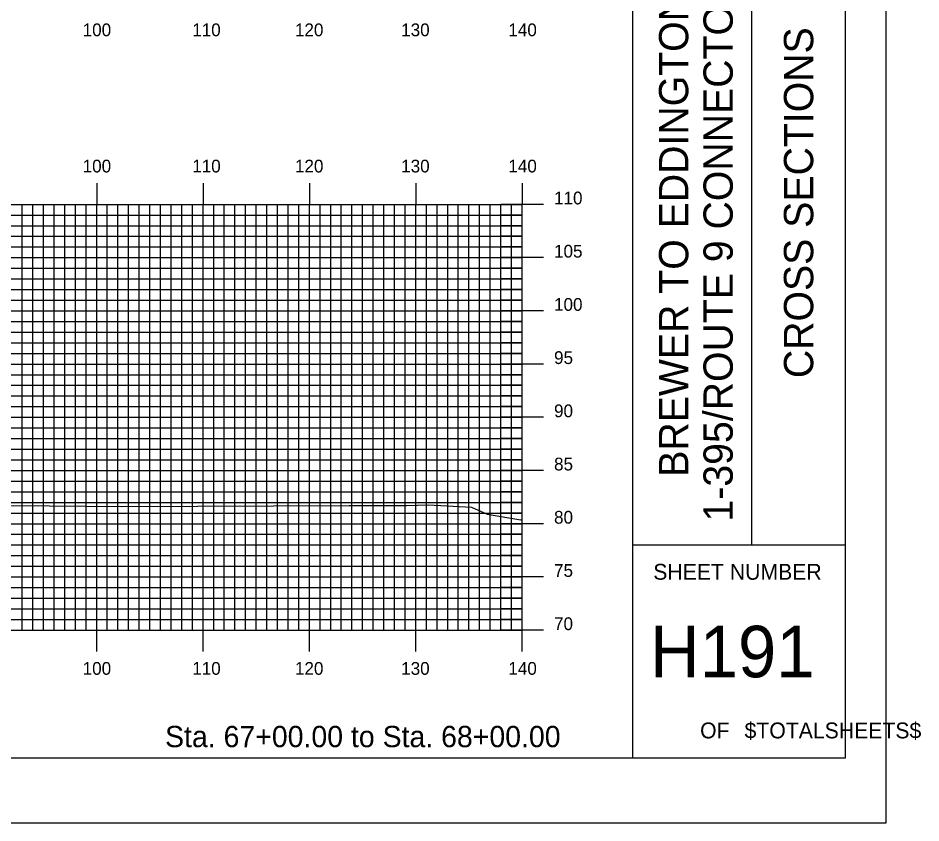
# Model space of a CAD drawing. Extents: x 1759430 to 1759773, y 442591 to 442811.
# Drawn here: x 1759688.3 to 1759773.2, y 442590.5 to 442666.2 of the extents above; entities that cross this region are included whole.
import ezdxf

# ---------------------------------------------------------------- set-up
doc = ezdxf.new("R2010")
doc.units = 0
for name, color, linetype in [('BORDER', 7, 'Continuous'), ('H_V ANNOTATION', 7, 'Continuous'), ('MAJOR', 7, 'Continuous'), ('MINOR', 7, 'Continuous'), ('PLOT BOUNDARY', 7, 'Continuous'), ('S_Roadway_Centerline', 7, 'Continuous')]:
    doc.layers.add(name, color=color, linetype=linetype)

msp = doc.modelspace()

# ---------------------------------------------------------------- linework, layer by layer
at = {"layer": 'BORDER'}
for p, q in [((1759746.075, 442596.665), (1759746.075, 442806.665)), ((1759757.257, 442616.671), (1759757.257, 442686.671)), ((1759746.075, 442616.671), (1759766.075, 442616.671))]:
    msp.add_line(p, q, dxfattribs=at)
msp.add_lwpolyline([(1759446.075, 442596.665), (1759766.075, 442596.665), (1759766.075, 442806.665), (1759446.075, 442806.665)], close=True, dxfattribs=at)
at = {"layer": 'MAJOR'}
for p, q in [((1759695.675, 442650.669), (1759695.675, 442648.665)), ((1759705.675, 442650.669), (1759705.675, 442648.665)), ((1759715.675, 442650.669), (1759715.675, 442648.665)), ((1759725.675, 442650.669), (1759725.675, 442648.665)), ((1759735.675, 442650.669), (1759735.675, 442648.665)), ((1759455.675, 442648.665), (1759735.675, 442648.665)), ((1759455.675, 442648.665), (1759735.675, 442648.665)), ((1759695.675, 442608.665), (1759695.675, 442648.665)), ((1759705.675, 442608.665), (1759705.675, 442648.665)), ((1759715.675, 442608.665), (1759715.675, 442648.665)), ((1759725.675, 442608.665), (1759725.675, 442648.665)), ((1759737.679, 442648.665), (1759733.671, 442648.665)), ((1759735.675, 442608.665), (1759735.675, 442648.665)), ((1759735.675, 442608.665), (1759735.675, 442648.665)), ((1759455.675, 442643.665), (1759735.675, 442643.665)), ((1759737.679, 442643.665), (1759733.671, 442643.665)), ((1759455.675, 442638.665), (1759735.675, 442638.665)), ((1759737.679, 442638.665), (1759733.671, 442638.665)), ((1759455.675, 442633.665), (1759735.675, 442633.665)), ((1759737.679, 442633.665), (1759733.671, 442633.665)), ((1759455.675, 442628.665), (1759735.675, 442628.665)), ((1759737.679, 442628.665), (1759733.671, 442628.665)), ((1759455.675, 442623.665), (1759735.675, 442623.665)), ((1759737.679, 442623.665), (1759733.671, 442623.665)), ((1759455.675, 442618.665), (1759735.675, 442618.665)), ((1759737.679, 442618.665), (1759733.671, 442618.665)), ((1759455.675, 442613.665), (1759735.675, 442613.665)), ((1759737.679, 442613.665), (1759733.671, 442613.665)), ((1759455.675, 442608.665), (1759735.675, 442608.665)), ((1759455.675, 442608.665), (1759735.675, 442608.665)), ((1759695.675, 442606.661), (1759695.675, 442608.665)), ((1759705.675, 442606.661), (1759705.675, 442608.665)), ((1759715.675, 442606.661), (1759715.675, 442608.665)), ((1759725.675, 442606.661), (1759725.675, 442608.665)), ((1759737.679, 442608.665), (1759733.671, 442608.665)), ((1759735.675, 442606.661), (1759735.675, 442608.665))]:
    msp.add_line(p, q, dxfattribs=at)
at = {"layer": 'MINOR'}
for p, q in [((1759688.675, 442608.665), (1759688.675, 442648.665)), ((1759689.675, 442608.665), (1759689.675, 442648.665)), ((1759690.675, 442608.665), (1759690.675, 442648.665)), ((1759691.675, 442608.665), (1759691.675, 442648.665)), ((1759692.675, 442608.665), (1759692.675, 442648.665)), ((1759693.675, 442608.665), (1759693.675, 442648.665)), ((1759694.675, 442608.665), (1759694.675, 442648.665)), ((1759696.675, 442608.665), (1759696.675, 442648.665)), ((1759697.675, 442608.665), (1759697.675, 442648.665)), ((1759698.675, 442608.665), (1759698.675, 442648.665)), ((1759699.675, 442608.665), (1759699.675, 442648.665)), ((1759700.675, 442608.665), (1759700.675, 442648.665)), ((1759701.675, 442608.665), (1759701.675, 442648.665)), ((1759702.675, 442608.665), (1759702.675, 442648.665)), ((1759703.675, 442608.665), (1759703.675, 442648.665)), ((1759704.675, 442608.665), (1759704.675, 442648.665)), ((1759706.675, 442608.665), (1759706.675, 442648.665)), ((1759707.675, 442608.665), (1759707.675, 442648.665)), ((1759708.675, 442608.665), (1759708.675, 442648.665)), ((1759709.675, 442608.665), (1759709.675, 442648.665)), ((1759710.675, 442608.665), (1759710.675, 442648.665)), ((1759711.675, 442608.665), (1759711.675, 442648.665)), ((1759712.675, 442608.665), (1759712.675, 442648.665)), ((1759713.675, 442608.665), (1759713.675, 442648.665)), ((1759714.675, 442608.665), (1759714.675, 442648.665)), ((1759716.675, 442608.665), (1759716.675, 442648.665)), ((1759717.675, 442608.665), (1759717.675, 442648.665)), ((1759718.675, 442608.665), (1759718.675, 442648.665)), ((1759719.675, 442608.665), (1759719.675, 442648.665)), ((1759720.675, 442608.665), (1759720.675, 442648.665)), ((1759721.675, 442608.665), (1759721.675, 442648.665)), ((1759722.675, 442608.665), (1759722.675, 442648.665)), ((1759723.675, 442608.665), (1759723.675, 442648.665)), ((1759724.675, 442608.665), (1759724.675, 442648.665)), ((1759726.675, 442608.665), (1759726.675, 442648.665)), ((1759727.675, 442608.665), (1759727.675, 442648.665)), ((1759728.675, 442608.665), (1759728.675, 442648.665)), ((1759729.675, 442608.665), (1759729.675, 442648.665)), ((1759730.675, 442608.665), (1759730.675, 442648.665)), ((1759731.675, 442608.665), (1759731.675, 442648.665)), ((1759732.675, 442608.665), (1759732.675, 442648.665)), ((1759733.675, 442608.665), (1759733.675, 442648.665)), ((1759734.675, 442608.665), (1759734.675, 442648.665)), ((1759455.675, 442647.665), (1759735.675, 442647.665)), ((1759735.675, 442647.665), (1759733.671, 442647.665)), ((1759455.675, 442646.665), (1759735.675, 442646.665)), ((1759735.675, 442646.665), (1759733.671, 442646.665)), ((1759455.675, 442645.665), (1759735.675, 442645.665)), ((1759735.675, 442645.665), (1759733.671, 442645.665)), ((1759455.675, 442644.665), (1759735.675, 442644.665)), ((1759735.675, 442644.665), (1759733.671, 442644.665)), ((1759455.675, 442642.665), (1759735.675, 442642.665)), ((1759735.675, 442642.665), (1759733.671, 442642.665)), ((1759455.675, 442641.665), (1759735.675, 442641.665)), ((1759735.675, 442641.665), (1759733.671, 442641.665)), ((1759455.675, 442640.665), (1759735.675, 442640.665)), ((1759735.675, 442640.665), (1759733.671, 442640.665)), ((1759455.675, 442639.665), (1759735.675, 442639.665)), ((1759735.675, 442639.665), (1759733.671, 442639.665)), ((1759455.675, 442637.665), (1759735.675, 442637.665)), ((1759735.675, 442637.665), (1759733.671, 442637.665)), ((1759455.675, 442636.665), (1759735.675, 442636.665)), ((1759735.675, 442636.665), (1759733.671, 442636.665)), ((1759455.675, 442635.665), (1759735.675, 442635.665)), ((1759735.675, 442635.665), (1759733.671, 442635.665)), ((1759455.675, 442634.665), (1759735.675, 442634.665)), ((1759735.675, 442634.665), (1759733.671, 442634.665)), ((1759455.675, 442632.665), (1759735.675, 442632.665)), ((1759735.675, 442632.665), (1759733.671, 442632.665)), ((1759455.675, 442631.665), (1759735.675, 442631.665)), ((1759735.675, 442631.665), (1759733.671, 442631.665)), ((1759455.675, 442630.665), (1759735.675, 442630.665)), ((1759735.675, 442630.665), (1759733.671, 442630.665)), ((1759455.675, 442629.665), (1759735.675, 442629.665)), ((1759735.675, 442629.665), (1759733.671, 442629.665)), ((1759455.675, 442627.665), (1759735.675, 442627.665)), ((1759735.675, 442627.665), (1759733.671, 442627.665)), ((1759455.675, 442626.665), (1759735.675, 442626.665)), ((1759735.675, 442626.665), (1759733.671, 442626.665)), ((1759455.675, 442625.665), (1759735.675, 442625.665)), ((1759735.675, 442625.665), (1759733.671, 442625.665)), ((1759455.675, 442624.665), (1759735.675, 442624.665)), ((1759735.675, 442624.665), (1759733.671, 442624.665)), ((1759455.675, 442622.665), (1759735.675, 442622.665)), ((1759735.675, 442622.665), (1759733.671, 442622.665)), ((1759455.675, 442621.665), (1759735.675, 442621.665)), ((1759735.675, 442621.665), (1759733.671, 442621.665)), ((1759455.675, 442620.665), (1759735.675, 442620.665)), ((1759735.675, 442620.665), (1759733.671, 442620.665)), ((1759455.675, 442619.665), (1759735.675, 442619.665)), ((1759735.675, 442619.665), (1759733.671, 442619.665)), ((1759455.675, 442617.665), (1759735.675, 442617.665)), ((1759735.675, 442617.665), (1759733.671, 442617.665)), ((1759455.675, 442616.665), (1759735.675, 442616.665)), ((1759735.675, 442616.665), (1759733.671, 442616.665)), ((1759455.675, 442615.665), (1759735.675, 442615.665)), ((1759735.675, 442615.665), (1759733.671, 442615.665)), ((1759455.675, 442614.665), (1759735.675, 442614.665)), ((1759735.675, 442614.665), (1759733.671, 442614.665)), ((1759455.675, 442612.665), (1759735.675, 442612.665)), ((1759735.675, 442612.665), (1759733.671, 442612.665)), ((1759455.675, 442611.665), (1759735.675, 442611.665)), ((1759735.675, 442611.665), (1759733.671, 442611.665)), ((1759455.675, 442610.665), (1759735.675, 442610.665)), ((1759735.675, 442610.665), (1759733.671, 442610.665)), ((1759455.675, 442609.665), (1759735.675, 442609.665)), ((1759735.675, 442609.665), (1759733.671, 442609.665))]:
    msp.add_line(p, q, dxfattribs=at)
at = {"layer": 'PLOT BOUNDARY'}
msp.add_lwpolyline([(1759429.888, 442590.547), (1759769.888, 442590.547), (1759769.888, 442810.547), (1759429.888, 442810.547)], close=True, dxfattribs=at)
at = {"layer": 'S_Roadway_Centerline'}
msp.add_lwpolyline([(1759561.872, 442618.604), (1759576.309, 442619.166), (1759587.344, 442619.444), (1759592.693, 442619.594), (1759597.581, 442619.598), (1759601.305, 442619.593), (1759617.374, 442619.724), (1759625.634, 442619.863), (1759637.407, 442620.074), (1759650.846, 442620.296), (1759655.335, 442620.298), (1759668.72, 442620.037), (1759673.506, 442620.296), (1759687.824, 442620.374), (1759698.026, 442620.27), (1759719.398, 442620.37), (1759724.818, 442620.359), (1759726.862, 442620.441), (1759730.905, 442620.214), (1759732.395, 442619.563), (1759735.561, 442619.02), (1759735.675, 442619.014)], dxfattribs=at)

# ---------------------------------------------------------------- texts
at = {"layer": 'BORDER'}
for s, p in [('1-395/ROUTE 9 CONNECTOR', (1759755.477, 442618.865)), ('BREWER TO EDDINGTON', (1759751.297, 442623.074)), ('CROSS SECTIONS', (1759763.044, 442632.339))]:
    msp.add_text(s, height=2.75575, rotation=90, dxfattribs=at).set_placement(p)
for s, height, p in [('SHEET NUMBER', 1.49054, (1759748.005, 442613.398)), ('H191', 4.8388, (1759747.697, 442604.23)), ('OF', 1.4905, (1759752.408, 442598.491)), ('$TOTALSHEETS$', 1.49054, (1759756.588, 442598.491))]:
    msp.add_text(s, height=height, dxfattribs=at).set_placement(p)
at = {"layer": 'H_V ANNOTATION'}
for s, height, p in [('100', 1.2, (1759694.358, 442664.465)), ('110', 1.2, (1759704.658, 442664.465)), ('120', 1.2, (1759714.315, 442664.465)), ('130', 1.2, (1759724.304, 442664.465)), ('140', 1.2, (1759734.379, 442664.465)), ('100', 1.2, (1759694.358, 442651.665)), ('110', 1.2, (1759704.658, 442651.665)), ('120', 1.2, (1759714.315, 442651.665)), ('130', 1.2, (1759724.304, 442651.665)), ('140', 1.2, (1759734.379, 442651.665)), ('110', 1.2, (1759738.675, 442648.665)), ('105', 1.2, (1759738.675, 442643.665)), ('100', 1.2, (1759738.675, 442638.665)), ('95', 1.2, (1759738.675, 442633.665)), ('90', 1.2, (1759738.675, 442628.665)), ('85', 1.2, (1759738.675, 442623.665)), ('80', 1.2, (1759738.675, 442618.665)), ('75', 1.2, (1759738.675, 442613.665)), ('70', 1.2, (1759738.675, 442608.665)), ('100', 1.2, (1759694.358, 442604.465)), ('110', 1.2, (1759704.658, 442604.465)), ('120', 1.2, (1759714.315, 442604.465)), ('130', 1.2, (1759724.304, 442604.465)), ('140', 1.2, (1759734.379, 442604.465)), ('Sta. 67+00.00 to Sta. 68+00.00', 2.0004, (1759702.105, 442597.665))]:
    msp.add_text(s, height=height, dxfattribs=at).set_placement(p)

doc.saveas('drawing.dxf')
